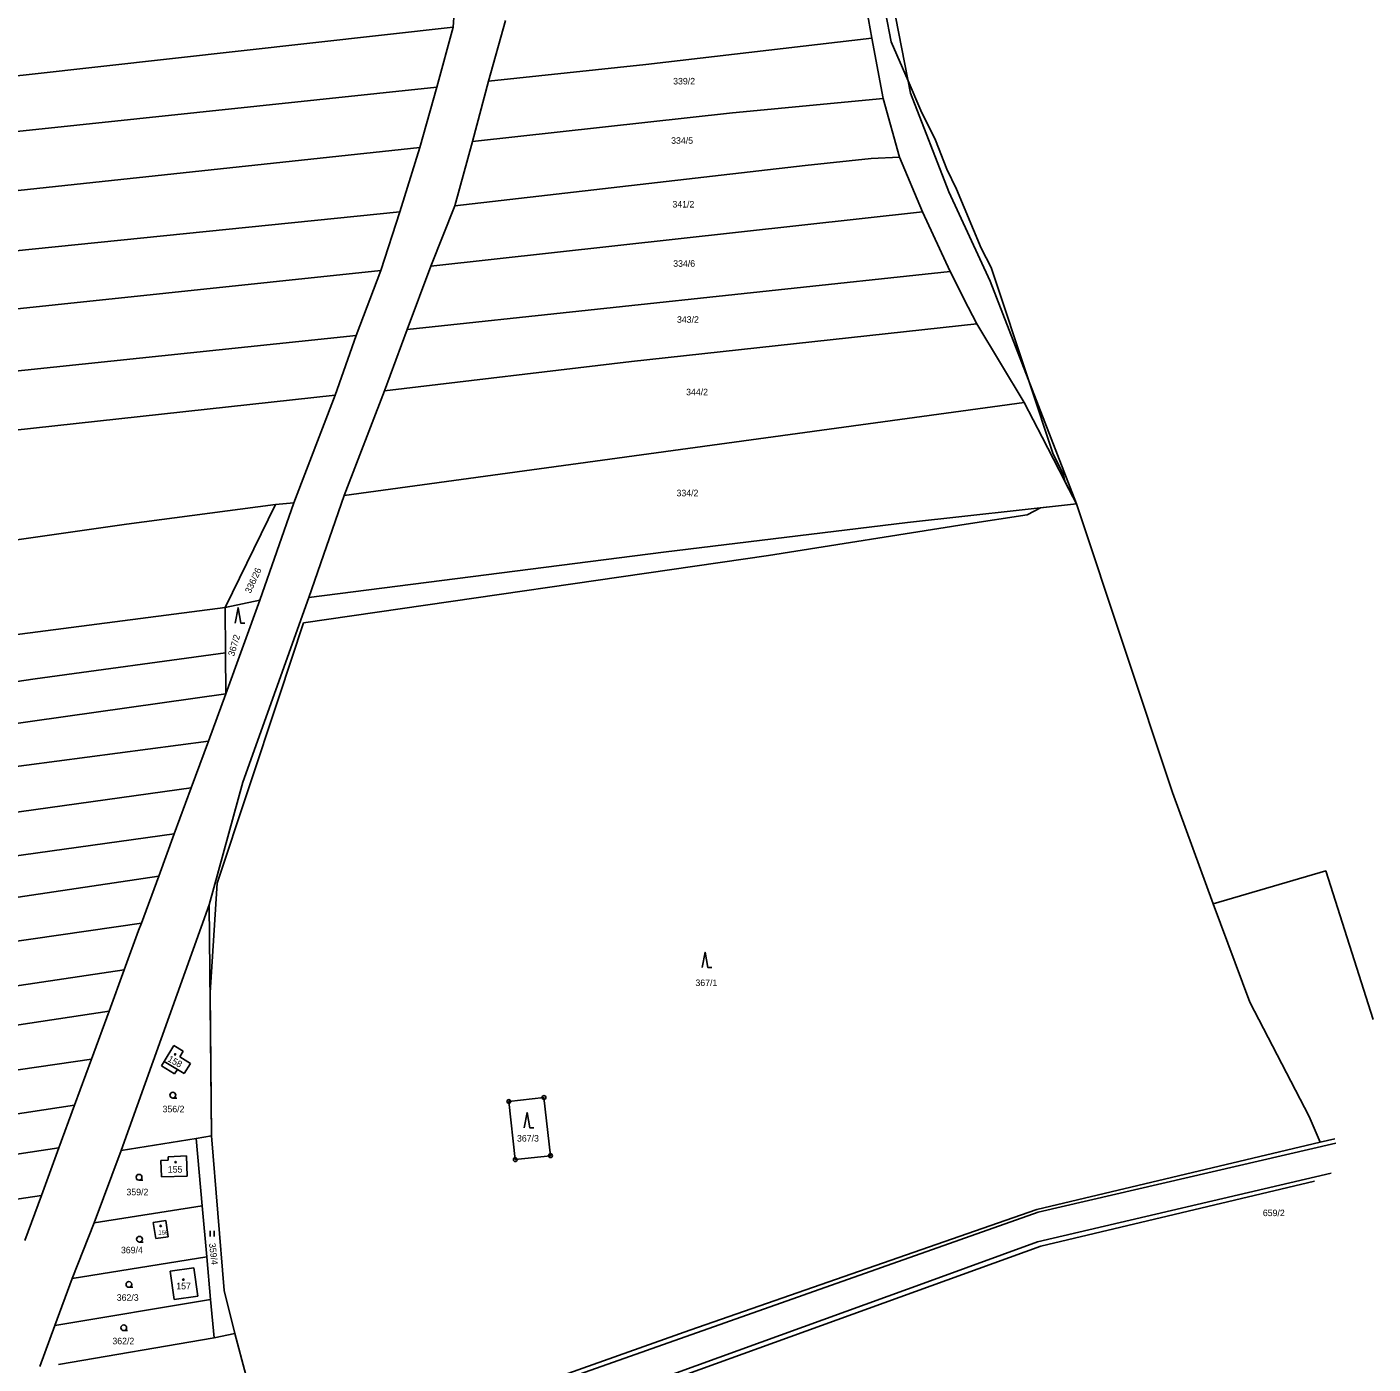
# Model space of a CAD drawing. Extents: x -747333 to -745433, y -1133152 to -1130600.
# Drawn here: x -745983.7 to -745633.9, y -1132218.2 to -1131870.7 of the extents above; entities that cross this region are included whole.
import ezdxf

# ---------------------------------------------------------------- set-up
doc = ezdxf.new("R2010")
doc.units = 0
for name, color, linetype in [('Vrstva 1', 7, 'Continuous'), ('Vrstva 16', 7, 'Continuous'), ('Vrstva 18', 7, 'Continuous'), ('Vrstva 19', 7, 'Continuous'), ('Vrstva 24', 7, 'Continuous'), ('Vrstva 25', 7, 'Continuous'), ('Vrstva 3', 7, 'Continuous'), ('Vrstva 37', 7, 'Continuous'), ('Vrstva 4', 7, 'Continuous'), ('Vrstva 52', 7, 'Continuous'), ('Vrstva 6', 7, 'Continuous')]:
    doc.layers.add(name, color=color, linetype=linetype)

msp = doc.modelspace()

# ---------------------------------------------------------------- linework, layer by layer
at = {"layer": 'Vrstva 1'}
for p, q in [((-745946.54, -1132194.11), (-745940.33, -1132193.21)), ((-745940.33, -1132193.21), (-745939.28, -1132200.55)), ((-745945.47, -1132201.43), (-745946.54, -1132194.11))]:
    msp.add_line(p, q, dxfattribs=at)
for points in [[(-745754.13, -1131887.99), (-745767.27, -1131820.58)], [(-745871.94, -1131855.43), (-745872.95, -1131870.82)], [(-745764.2, -1131873.68), (-745766.79, -1131859.01)], [(-745872.95, -1131870.82), (-745877.23, -1131886.38)], [(-745863.82, -1131884.81), (-745859.39, -1131869.11)], [(-745761.24, -1131889.32), (-745764.2, -1131873.68)], [(-745867.95, -1131900.51), (-745863.82, -1131884.81)], [(-745877.23, -1131886.38), (-745881.66, -1131902.09)], [(-745756.96, -1131904.59), (-745761.24, -1131889.32)], [(-745744.13, -1131913.56), (-745754.13, -1131887.99)], [(-745881.66, -1131902.09), (-745886.79, -1131918.79)], [(-745872.52, -1131917.22), (-745867.95, -1131900.51)], [(-745750.96, -1131918.81), (-745756.96, -1131904.59)], [(-745733.42, -1131936.84), (-745744.13, -1131913.56)], [(-745878.8, -1131932.92), (-745872.52, -1131917.22)], [(-745886.79, -1131918.79), (-745891.79, -1131934.06)], [(-745743.82, -1131934.33), (-745750.96, -1131918.81)], [(-745891.79, -1131934.06), (-745898.21, -1131950.9)], [(-745884.94, -1131949.34), (-745878.8, -1131932.92)], [(-745739.12, -1131943.61), (-745743.82, -1131934.33)], [(-745711.01, -1131994.68), (-745733.42, -1131936.84)], [(-745736.9, -1131947.9), (-745739.12, -1131943.61)], [(-745724.54, -1131968.33), (-745736.9, -1131947.9)], [(-745898.21, -1131950.9), (-745903.63, -1131966.47)], [(-745890.79, -1131965.32), (-745884.94, -1131949.34)], [(-745901.28, -1131992.52), (-745890.79, -1131965.32)], [(-745903.63, -1131966.47), (-745914.34, -1131994.45)], [(-745719.9, -1131977.35), (-745724.54, -1131968.33)], [(-745711.01, -1131994.68), (-745719.9, -1131977.35)], [(-745910.48, -1132019), (-745901.28, -1131992.52)], [(-745914.34, -1131994.45), (-745923.19, -1132019.72)], [(-745754.91, -1131999.55), (-745711.01, -1131994.68)], [(-745686.03, -1132069.66), (-745711.01, -1131994.68)], [(-745818.32, -1132007.28), (-745754.91, -1131999.55)], [(-745910.48, -1132019), (-745818.32, -1132007.28)], [(-745923.19, -1132019.72), (-745932.19, -1132021.63)], [(-745932.19, -1132021.63), (-745932.15, -1132033.44)], [(-745932.04, -1132044.03), (-745923.19, -1132019.72)], [(-745927.61, -1132066.97), (-745910.48, -1132019)], [(-745932.15, -1132033.44), (-745932.04, -1132044.03)], [(-745932.04, -1132044.03), (-745936.55, -1132056.36)], [(-745936.55, -1132056.36), (-745941.03, -1132068.49)], [(-745936.33, -1132098.92), (-745927.61, -1132066.97)], [(-745941.03, -1132068.49), (-745945.43, -1132080.44)], [(-745675.46, -1132098.66), (-745686.03, -1132069.66)], [(-745945.43, -1132080.44), (-745949.48, -1132091.43)], [(-745949.48, -1132091.43), (-745953.97, -1132103.62)], [(-745646.19, -1132090.09), (-745675.46, -1132098.66)], [(-745936.33, -1132098.92), (-745959.25, -1132162.69)], [(-745935.75, -1132158.93), (-745936.33, -1132098.92)], [(-745675.46, -1132098.66), (-745665.9, -1132124.22)], [(-745954.69, -1132105.56), (-745958.45, -1132115.81)], [(-745953.97, -1132103.62), (-745954.69, -1132105.56)], [(-745958.45, -1132115.81), (-745962.38, -1132126.51)], [(-745962.38, -1132126.51), (-745966.97, -1132139.01)], [(-745665.9, -1132124.22), (-745650.48, -1132153.93)], [(-745948.04, -1132139.57), (-745945.54, -1132135.46)], [(-745945.54, -1132135.46), (-745943.14, -1132136.92)], [(-745943.14, -1132136.92), (-745944.02, -1132138.37)], [(-745966.97, -1132139.01), (-745971.37, -1132150.98)], [(-745948.77, -1132140.77), (-745948.04, -1132139.57)], [(-745945.35, -1132142.85), (-745948.77, -1132140.77)], [(-745944.02, -1132138.37), (-745941.2, -1132140.09)], [(-745941.2, -1132140.09), (-745942.83, -1132142.74)], [(-745944.62, -1132141.65), (-745945.35, -1132142.85)], [(-745942.83, -1132142.74), (-745944.62, -1132141.65)], [(-745971.37, -1132150.98), (-745975.43, -1132162.05)], [(-745858.51, -1132149.99), (-745849.36, -1132148.97)], [(-745856.82, -1132165.1), (-745858.51, -1132149.99)], [(-745849.36, -1132148.97), (-745847.68, -1132164.08)], [(-745975.43, -1132162.05), (-745979.96, -1132174.39)], [(-745959.25, -1132162.69), (-745939.77, -1132159.57)], [(-745939.77, -1132159.57), (-745935.75, -1132158.93)], [(-745939.77, -1132159.57), (-745938.19, -1132177.11)], [(-745935.75, -1132158.93), (-745932.48, -1132199.11)], [(-745721.32, -1132178.1), (-745647.66, -1132160.59)], [(-745966.27, -1132181.55), (-745959.25, -1132162.69)], [(-745948.92, -1132165.35), (-745946.99, -1132165.28)], [(-745948.77, -1132169.6), (-745948.92, -1132165.35)], [(-745947.02, -1132164.42), (-745942.28, -1132164.15)], [(-745946.99, -1132165.28), (-745947.02, -1132164.42)], [(-745942.28, -1132164.15), (-745942.1, -1132169.36)], [(-745847.68, -1132164.08), (-745856.82, -1132165.1)], [(-745942.1, -1132169.36), (-745948.77, -1132169.6)], [(-745649.16, -1132170.73), (-745720.29, -1132187.56)], [(-745979.96, -1132174.39), (-745984.27, -1132186.11)], [(-745938.19, -1132177.11), (-745966.27, -1132181.55)], [(-745937, -1132190.37), (-745938.19, -1132177.11)], [(-745811.48, -1132209.43), (-745721.32, -1132178.1)], [(-745966.27, -1132181.55), (-745971.96, -1132195.98)], [(-745950.88, -1132181.43), (-745947.66, -1132180.91)], [(-745950.26, -1132185.62), (-745950.88, -1132181.43)], [(-745947.66, -1132180.91), (-745947.05, -1132185.16)], [(-745947.05, -1132185.16), (-745950.26, -1132185.62)], [(-745720.29, -1132187.56), (-745882.17, -1132246.18)], [(-745971.96, -1132195.98), (-745937, -1132190.37)], [(-745937, -1132190.37), (-745936, -1132201.44)], [(-745976.45, -1132208.21), (-745971.96, -1132195.98)], [(-745939.28, -1132200.55), (-745945.47, -1132201.43)], [(-745932.48, -1132199.11), (-745929.68, -1132210.31)], [(-745936, -1132201.44), (-745976.45, -1132208.21)], [(-745935.1, -1132211.4), (-745936, -1132201.44)], [(-745976.45, -1132208.21), (-745980.37, -1132218.89)], [(-745935.1, -1132211.4), (-745929.68, -1132210.31)], [(-745929.68, -1132210.31), (-745926.88, -1132221.06)], [(-745874.83, -1132231.96), (-745811.48, -1132209.43)], [(-745975.56, -1132218.31), (-745935.1, -1132211.4)]]:
    msp.add_lwpolyline(points, dxfattribs=at)
at = {"layer": 'Vrstva 24'}
for p, q in [((-745858.56, -1132149.99), (-745858.46, -1132149.99)), ((-745849.41, -1132148.97), (-745849.31, -1132148.97)), ((-745856.87, -1132165.1), (-745856.77, -1132165.1)), ((-745847.73, -1132164.08), (-745847.63, -1132164.08))]:
    msp.add_line(p, q, dxfattribs=at)
for centre in [(-745858.51, -1132149.99), (-745849.36, -1132148.97), (-745856.82, -1132165.1), (-745847.68, -1132164.08)]:
    msp.add_circle(centre, 0.499289, dxfattribs=at)
at = {"layer": 'Vrstva 25'}
for p, q in [((-745945.8, -1132149.1), (-745944.8, -1132149.1)), ((-745954.59, -1132170.45), (-745953.59, -1132170.45)), ((-745954.48, -1132186.54), (-745953.48, -1132186.54)), ((-745936.07, -1132183.62), (-745936.07, -1132185.12)), ((-745935.07, -1132185.12), (-745935.07, -1132183.62)), ((-745957.21, -1132198.29), (-745956.21, -1132198.29)), ((-745958.57, -1132209.54), (-745957.57, -1132209.54))]:
    msp.add_line(p, q, dxfattribs=at)
for points in [[(-745929.6, -1132025.7), (-745928.85, -1132021.7), (-745928.1, -1132025.7), (-745927.1, -1132025.7)], [(-745808.24, -1132115.2), (-745807.49, -1132111.2), (-745806.74, -1132115.2), (-745805.74, -1132115.2)], [(-745854.51, -1132156.86), (-745853.76, -1132152.86), (-745853.01, -1132156.86), (-745852.01, -1132156.86)]]:
    msp.add_lwpolyline(points, dxfattribs=at)
for centre, radius in [((-745945.2, -1132137.75), 0.174503), ((-745945.8, -1132148.35), 0.75), ((-745945.09, -1132165.76), 0.174503), ((-745954.59, -1132169.7), 0.75), ((-745948.97, -1132182.35), 0.174503), ((-745954.48, -1132185.79), 0.75), ((-745957.21, -1132197.54), 0.75), ((-745943.08, -1132196.28), 0.174503), ((-745958.57, -1132208.79), 0.75)]:
    msp.add_circle(centre, radius, dxfattribs=at)
at = {"layer": 'Vrstva 3'}
for points in [[(-745948.04, -1132139.57), (-745945.54, -1132135.46)], [(-745945.54, -1132135.46), (-745943.14, -1132136.92)], [(-745943.14, -1132136.92), (-745944.02, -1132138.37)], [(-745948.04, -1132139.57), (-745944.62, -1132141.65)], [(-745944.02, -1132138.37), (-745941.2, -1132140.09)], [(-745941.2, -1132140.09), (-745942.83, -1132142.74)], [(-745942.83, -1132142.74), (-745944.62, -1132141.65)], [(-745948.92, -1132165.35), (-745946.99, -1132165.28)], [(-745948.77, -1132169.6), (-745948.92, -1132165.35)], [(-745947.02, -1132164.42), (-745942.28, -1132164.15)], [(-745946.99, -1132165.28), (-745947.02, -1132164.42)], [(-745942.28, -1132164.15), (-745942.1, -1132169.36)], [(-745942.1, -1132169.36), (-745948.77, -1132169.6)], [(-745950.88, -1132181.43), (-745947.66, -1132180.91)], [(-745950.26, -1132185.62), (-745950.88, -1132181.43)], [(-745947.66, -1132180.91), (-745947.05, -1132185.16)], [(-745947.05, -1132185.16), (-745950.26, -1132185.62)], [(-745946.54, -1132194.11), (-745940.33, -1132193.21)], [(-745940.33, -1132193.21), (-745939.28, -1132200.55)], [(-745945.47, -1132201.43), (-745946.54, -1132194.11)], [(-745939.28, -1132200.55), (-745945.47, -1132201.43)]]:
    msp.add_lwpolyline(points, dxfattribs=at)
at = {"layer": 'Vrstva 37'}
for centre in [(-745945.2, -1132137.75), (-745945.09, -1132165.76), (-745948.97, -1132182.35), (-745943.08, -1132196.28)]:
    msp.add_circle(centre, 0.174503, dxfattribs=at)
at = {"layer": 'Vrstva 4'}
for points in [[(-745948.04, -1132139.57), (-745944.62, -1132141.65)], [(-745643.59, -1132160.8), (-745720.93, -1132178.79)], [(-745721.14, -1132186.49), (-745644.8, -1132168.59)], [(-745720.93, -1132178.79), (-745883.78, -1132236.25)], [(-745748.89, -1132196.6), (-745721.14, -1132186.49)], [(-745842.87, -1132230.67), (-745748.89, -1132196.6)]]:
    msp.add_lwpolyline(points, dxfattribs=at)
at = {"layer": 'Vrstva 52'}
for points in [[(-745926.88, -1132221.06), (-745929.68, -1132210.31), (-745932.48, -1132199.11), (-745935.75, -1132158.93), (-745936.11, -1132121.64), (-745935.62, -1132113.62), (-745934.31, -1132093.25), (-745918.19, -1132044.75), (-745911.81, -1132025.63), (-745791, -1132008.12), (-745739.62, -1132000), (-745723.81, -1131997.5), (-745720.37, -1131995.72), (-745711.01, -1131994.68), (-745713.92, -1131989.02), (-745714.44, -1131986.87), (-745717, -1131981.75), (-745723.09, -1131963.49), (-745733.19, -1131933.25), (-745735.75, -1131928.25), (-745742.12, -1131912.88), (-745744.69, -1131907.75), (-745747.63, -1131900.13), (-745751.44, -1131892.5), (-745754.75, -1131884.79), (-745759.13, -1131874.62), (-745765.06, -1131844)], [(-745633.91, -1132128.65), (-745646.19, -1132090.09), (-745675.46, -1132098.66), (-745665.9, -1132124.22), (-745650.48, -1132153.93), (-745647.66, -1132160.59), (-745643.88, -1132159.73)]]:
    msp.add_lwpolyline(points, dxfattribs=at)
at = {"layer": 'Vrstva 6'}
for points in [[(-745983.18, -1131883.12), (-745872.95, -1131870.82)], [(-745822.88, -1131880.52), (-745764.2, -1131873.68)], [(-745863.82, -1131884.81), (-745822.88, -1131880.52)], [(-746129.29, -1131898.95), (-745983.18, -1131883.12)], [(-745986.39, -1131897.96), (-745877.23, -1131886.38)], [(-745800.34, -1131893.03), (-745761.24, -1131889.32)], [(-745867.95, -1131900.51), (-745800.34, -1131893.03)], [(-746058.97, -1131921.07), (-745881.66, -1131902.09)], [(-745872.52, -1131917.22), (-745781.5, -1131906.78)], [(-745781.5, -1131906.78), (-745764.37, -1131904.93)], [(-745764.37, -1131904.93), (-745756.96, -1131904.59)], [(-745987.44, -1131929), (-745886.79, -1131918.79)], [(-745878.8, -1131932.92), (-745750.96, -1131918.81)], [(-746061.11, -1131951.9), (-745891.79, -1131934.06)], [(-745884.94, -1131949.34), (-745743.82, -1131934.33)], [(-745826.6, -1131957.68), (-745736.9, -1131947.9)], [(-746076.23, -1131969.6), (-745898.21, -1131950.9)], [(-745890.79, -1131965.32), (-745826.6, -1131957.68)], [(-746054.91, -1131982.95), (-745903.63, -1131966.47)], [(-745901.28, -1131992.52), (-745724.54, -1131968.33)], [(-745957.87, -1131999.93), (-745919.09, -1131994.88)], [(-745932.19, -1132021.63), (-745919.09, -1131994.88)], [(-745919.09, -1131994.88), (-745914.34, -1131994.45)], [(-745989.96, -1132004.59), (-745957.87, -1131999.93)], [(-745987.52, -1132028.78), (-745932.19, -1132021.63)], [(-745981.57, -1132040.17), (-745932.15, -1132033.44)], [(-746124.91, -1132061.34), (-745981.57, -1132040.17)], [(-746024.65, -1132057.16), (-745932.04, -1132044.03)], [(-746007.53, -1132065.72), (-745936.55, -1132056.36)], [(-746121.22, -1132093.59), (-745941.03, -1132068.49)], [(-746120.21, -1132104.74), (-745945.43, -1132080.44)], [(-746023.23, -1132102.4), (-745949.48, -1132091.43)], [(-746117.56, -1132127.27), (-745953.97, -1132103.62)], [(-746055.48, -1132130.24), (-745958.45, -1132115.81)], [(-746049.48, -1132139.66), (-745962.38, -1132126.51)], [(-746113.52, -1132160.29), (-745966.97, -1132139.01)], [(-746072.74, -1132166.35), (-745971.37, -1132150.98)], [(-746083.31, -1132178.32), (-745975.43, -1132162.05)], [(-746109.23, -1132193.62), (-745979.96, -1132174.39)]]:
    msp.add_lwpolyline(points, dxfattribs=at)

# ---------------------------------------------------------------- texts
at = {"layer": 'Vrstva 16'}
msp.add_text('659/2', height=1.7, dxfattribs=at).set_placement((-745662.549961, -1132179.79))
at = {"layer": 'Vrstva 18'}
for s, p in [('339/2', (-745815.79, -1131885.69)), ('334/5', (-745816.31, -1131901.11)), ('341/2', (-745815.98, -1131917.67)), ('334/6', (-745815.78, -1131933.08)), ('343/2', (-745814.8, -1131947.63)), ('344/2', (-745812.43, -1131966.47)), ('334/2', (-745814.92, -1131992.72)), ('367/1', (-745810, -1132120)), ('356/2', (-745948.48, -1132152.81)), ('367/3', (-745856.38, -1132160.41)), ('359/2', (-745957.86, -1132174.38)), ('369/4', (-745959.29, -1132189.45)), ('362/3', (-745960.38, -1132201.79)), ('362/2', (-745961.52, -1132213.09))]:
    msp.add_text(s, height=1.7, dxfattribs=at).set_placement(p)
for s, rotation, p in [('336/26', 65.21031, (-745925.61, -1132018.08)), ('367/2', 73.63278, (-745929.888533, -1132034.403465)), ('359/4', 276.95673, (-745936.43, -1132186.89))]:
    msp.add_text(s, height=1.7, rotation=rotation, dxfattribs=at).set_placement(p)
at = {"layer": 'Vrstva 19'}
msp.add_text('158', height=1.7, rotation=331.55703, dxfattribs=at).set_placement((-745947.31, -1132139.47))
for s, height, p in [('155', 1.7, (-745947.11, -1132168.49)), ('156', 1.14, (-745949.57, -1132184.59)), ('157', 1.7, (-745944.91, -1132198.81))]:
    msp.add_text(s, height=height, dxfattribs=at).set_placement(p)

doc.saveas('drawing.dxf')
